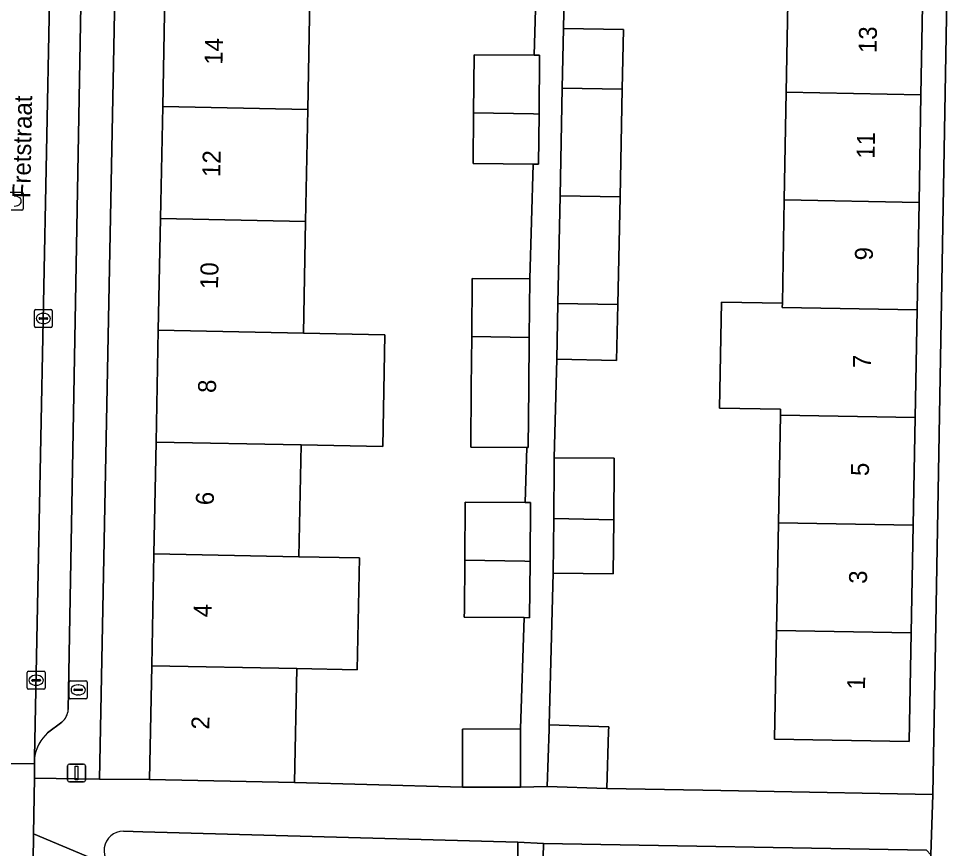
# Model space of a CAD drawing. Extents: x 160023 to 161302, y 384750 to 385707.
# Drawn here: x 160677 to 160728.6, y 385019.8 to 385066.1 of the extents above; entities that cross this region are included whole.
import ezdxf

# ---------------------------------------------------------------- set-up
doc = ezdxf.new("R2010")
doc.units = 0
for name, color, linetype in [('IMGEO_Brandkraan', 7, 'Continuous'), ('IMGEO_Erf', 7, 'Continuous'), ('IMGEO_Groenvoorziening', 7, 'Continuous'), ('IMGEO_Kolk', 7, 'Continuous'), ('IMGEO_Lichtmast', 7, 'Continuous'), ('IMGEO_Muur', 7, 'Continuous'), ('IMGEO_Openbare_ruimte_label', 7, 'Continuous'), ('IMGEO_Pand', 7, 'Continuous'), ('IMGEO_Pand_nummerreeks', 7, 'Continuous'), ('IMGEO_Parkeervlak_open', 7, 'Continuous'), ('IMGEO_Rijbaan_lokaal_gesloten', 7, 'Continuous'), ('IMGEO_Rijbaan_lokaal_open', 7, 'Continuous'), ('IMGEO_Rioolput', 7, 'Continuous'), ('IMGEO_Voetpad_open', 7, 'Continuous')]:
    doc.layers.add(name, color=color, linetype=linetype)

msp = doc.modelspace()

# ---------------------------------------------------------------- linework, layer by layer
at = {"layer": 'IMGEO_Brandkraan'}
for p, q in [((160679.828, 385028.254), (160679.828, 385029.106)), ((160679.903, 385029.18), (160680.755, 385029.18)), ((160680.829, 385029.106), (160680.829, 385028.254)), ((160680.087, 385028.674), (160680.087, 385028.686)), ((160680.525, 385028.637), (160680.127, 385028.637)), ((160680.13, 385028.723), (160680.528, 385028.723)), ((160680.316, 385028.96), (160680.341, 385028.96)), ((160680.571, 385028.686), (160680.571, 385028.674)), ((160680.755, 385028.18), (160679.903, 385028.18)), ((160680.339, 385028.4), (160680.314, 385028.4))]:
    msp.add_line(p, q, dxfattribs=at)
for points in [[(160679.828, 385028.254), (160679.828, 385029.106)], [(160679.903, 385029.18), (160680.755, 385029.18)], [(160680.829, 385029.106), (160680.829, 385028.254)], [(160680.755, 385028.18), (160679.903, 385028.18)]]:
    msp.add_lwpolyline(points, dxfattribs=at)
for centre, radius, start, end in [((160679.905, 385029.104), 0.0765, 91.552, 178.448), ((160679.905, 385029.104), 0.0765, 91.552, 178.448), ((160680.753, 385029.104), 0.0765, 1.552, 88.448), ((160680.753, 385029.104), 0.0765, 1.552, 88.448), ((160680.127, 385028.683), 0.0403, 85.8775, 175.7526), ((160680.124, 385028.673), 0.0366, 178.938, 274.7102), ((160680.528, 385028.68), 0.043, 264.8664, 352.4533), ((160680.532, 385028.685), 0.0386, 1.7309, 96.639), ((160679.905, 385028.256), 0.0765, 181.552, 268.448), ((160679.905, 385028.256), 0.0765, 181.552, 268.448), ((160680.753, 385028.256), 0.0765, 271.552, 358.448), ((160680.753, 385028.256), 0.0765, 271.552, 358.448)]:
    msp.add_arc(centre, radius, start, end, dxfattribs=at)
for centre, major_axis, ratio, start_param, end_param in [((160680.315, 385028.68), (-0.387, 0.002), 0.722429, 4.712389, 7.853982), ((160680.34, 385028.68), (-0.39, 0.002), 0.717154, 1.570796, 4.712389)]:
    msp.add_ellipse(centre, major_axis=major_axis, ratio=ratio, start_param=start_param, end_param=end_param, dxfattribs=at)
at = {"layer": 'IMGEO_Erf'}
msp.add_lwpolyline([(160682.973, 385098.744), (160681.51, 385023.71), (160684.298, 385023.676), (160684.423, 385030.023), (160684.546, 385036.256), (160684.67, 385042.49), (160684.793, 385048.724), (160684.916, 385054.958), (160685.039, 385061.192), (160685.162, 385067.425), (160685.285, 385073.659), (160685.408, 385079.893), (160685.531, 385086.127), (160685.655, 385092.36), (160685.78, 385098.711)], close=True, dxfattribs=at)
for points in [[(160707.438, 385068.318), (160707.381, 385065.557), (160710.722, 385065.487), (160710.652, 385062.16), (160710.527, 385056.16), (160710.402, 385050.161), (160710.337, 385047.05), (160706.998, 385047.12), (160706.865, 385041.619), (160710.209, 385041.591), (160710.206, 385041.222), (160710.18, 385038.163), (160710.154, 385035.153), (160706.81, 385035.182), (160706.581, 385026.724), (160709.897, 385026.616), (160709.889, 385026.38), (160709.785, 385023.182), (160715.135, 385023.083), (160718.134, 385023.028), (160727.96, 385022.845), (160729.292, 385097.92)], [(160693.246, 385067.266), (160693.122, 385061.033), (160692.999, 385054.799), (160692.876, 385048.565), (160697.421, 385048.476), (160697.298, 385042.242), (160692.753, 385042.331), (160692.63, 385036.097), (160695.998, 385036.031), (160695.876, 385029.798), (160692.506, 385029.864), (160692.381, 385023.516), (160696.42, 385023.404), (160701.751, 385023.256), (160701.743, 385026.495), (160704.972, 385026.502), (160705.184, 385032.705), (160701.849, 385032.734), (160701.852, 385033.081), (160701.877, 385035.915), (160701.904, 385039.149), (160705.248, 385039.121), (160705.341, 385042.19), (160702.208, 385042.217), (160702.238, 385045.548), (160702.262, 385048.38), (160702.291, 385051.616), (160705.494, 385051.589), (160705.688, 385057.988), (160702.344, 385058.017), (160702.369, 385060.851), (160702.396, 385064.085), (160705.74, 385064.057), (160705.935, 385070.455)], [(160727.413, 385067.857), (160727.304, 385061.858), (160727.195, 385055.858), (160727.086, 385049.859), (160726.978, 385043.86), (160726.869, 385037.861), (160726.76, 385031.862), (160726.65, 385025.798), (160719.138, 385025.934), (160719.248, 385031.998), (160719.357, 385037.997), (160719.466, 385043.996), (160719.472, 385044.323), (160716.076, 385044.384), (160716.182, 385050.299), (160719.578, 385050.238), (160719.683, 385055.994), (160719.792, 385061.994), (160719.901, 385067.993)]]:
    msp.add_lwpolyline(points, dxfattribs=at)
at = {"layer": 'IMGEO_Groenvoorziening'}
for points in [[(160683.921, 385020.768), (160682.843, 385020.799)], [(160704.782, 385014.119), (160704.836, 385020.196), (160683.921, 385020.768)]]:
    msp.add_lwpolyline(points, dxfattribs=at)
msp.add_lwpolyline([(160727.743, 385013.364), (160727.856, 385019.479), (160727.606, 385019.739), (160706.266, 385020.111), (160706.111, 385014.075)], close=True, dxfattribs=at)
msp.add_arc((160682.836, 385019.732), 1.067, 89.6283, 254.617, dxfattribs=at)
at = {"layer": 'IMGEO_Kolk'}
for p, q in [((160677.883, 385048.957), (160677.883, 385049.809)), ((160677.958, 385049.883), (160678.81, 385049.883)), ((160678.371, 385049.663), (160678.396, 385049.663)), ((160678.884, 385049.809), (160678.884, 385048.957)), ((160678.142, 385049.377), (160678.142, 385049.389)), ((160678.58, 385049.34), (160678.182, 385049.34)), ((160678.185, 385049.426), (160678.583, 385049.426)), ((160678.394, 385049.103), (160678.369, 385049.103)), ((160678.626, 385049.389), (160678.626, 385049.377)), ((160678.81, 385048.883), (160677.958, 385048.883)), ((160677.484, 385028.787), (160677.484, 385029.639)), ((160677.559, 385029.713), (160678.411, 385029.713)), ((160677.972, 385029.493), (160677.997, 385029.493)), ((160678.485, 385029.639), (160678.485, 385028.787)), ((160677.743, 385029.207), (160677.743, 385029.219)), ((160678.181, 385029.17), (160677.783, 385029.17)), ((160677.786, 385029.256), (160678.184, 385029.256)), ((160678.227, 385029.219), (160678.227, 385029.207)), ((160678.411, 385028.713), (160677.559, 385028.713)), ((160677.995, 385028.933), (160677.97, 385028.933))]:
    msp.add_line(p, q, dxfattribs=at)
for points in [[(160677.883, 385048.957), (160677.883, 385049.809)], [(160677.958, 385049.883), (160678.81, 385049.883)], [(160678.884, 385049.809), (160678.884, 385048.957)], [(160678.81, 385048.883), (160677.958, 385048.883)], [(160677.484, 385028.787), (160677.484, 385029.639)], [(160677.559, 385029.713), (160678.411, 385029.713)], [(160678.485, 385029.639), (160678.485, 385028.787)], [(160678.411, 385028.713), (160677.559, 385028.713)]]:
    msp.add_lwpolyline(points, dxfattribs=at)
for centre, radius, start, end in [((160677.96, 385049.807), 0.0765, 91.552, 178.448), ((160677.96, 385049.807), 0.0765, 91.552, 178.448), ((160678.808, 385049.807), 0.0765, 1.552, 88.448), ((160678.808, 385049.807), 0.0765, 1.552, 88.448), ((160678.182, 385049.386), 0.0403, 85.8775, 175.7526), ((160678.179, 385049.376), 0.0366, 178.938, 274.7102), ((160678.583, 385049.383), 0.043, 264.8664, 352.4533), ((160678.587, 385049.388), 0.0386, 1.7309, 96.639), ((160677.96, 385048.959), 0.0765, 181.552, 268.448), ((160677.96, 385048.959), 0.0765, 181.552, 268.448), ((160678.808, 385048.959), 0.0765, 271.552, 358.448), ((160678.808, 385048.959), 0.0765, 271.552, 358.448), ((160677.561, 385029.637), 0.0765, 91.552, 178.448), ((160677.561, 385029.637), 0.0765, 91.552, 178.448), ((160678.409, 385029.637), 0.0765, 1.552, 88.448), ((160678.409, 385029.637), 0.0765, 1.552, 88.448), ((160677.783, 385029.216), 0.0403, 85.8775, 175.7526), ((160677.78, 385029.206), 0.0366, 178.938, 274.7102), ((160678.184, 385029.213), 0.043, 264.8664, 352.4533), ((160678.188, 385029.218), 0.0386, 1.7309, 96.639), ((160677.561, 385028.789), 0.0765, 181.552, 268.448), ((160677.561, 385028.789), 0.0765, 181.552, 268.448), ((160678.409, 385028.789), 0.0765, 271.552, 358.448), ((160678.409, 385028.789), 0.0765, 271.552, 358.448)]:
    msp.add_arc(centre, radius, start, end, dxfattribs=at)
for centre, major_axis, ratio, start_param, end_param in [((160678.37, 385049.383), (-0.387, 0.002), 0.722429, 4.712389, 7.853982), ((160678.395, 385049.383), (-0.39, 0.002), 0.717154, 1.570796, 4.712389), ((160677.971, 385029.213), (-0.387, 0.002), 0.722429, 4.712389, 7.853982), ((160677.996, 385029.213), (-0.39, 0.002), 0.717154, 1.570796, 4.712389)]:
    msp.add_ellipse(centre, major_axis=major_axis, ratio=ratio, start_param=start_param, end_param=end_param, dxfattribs=at)
at = {"layer": 'IMGEO_Lichtmast'}
for p, q in [((160679.738, 385023.645), (160679.738, 385024.445)), ((160679.738, 385024.445), (160679.738, 385023.645)), ((160679.838, 385024.545), (160680.628, 385024.545)), ((160680.628, 385024.545), (160679.838, 385024.545)), ((160680.728, 385024.445), (160680.728, 385023.645)), ((160680.728, 385023.645), (160680.728, 385024.445)), ((160680.628, 385023.545), (160679.838, 385023.545)), ((160679.838, 385023.545), (160680.628, 385023.545))]:
    msp.add_line(p, q, dxfattribs=at)
msp.add_lwpolyline([(160680.158, 385024.42), (160680.308, 385024.42), (160680.308, 385023.67), (160680.158, 385023.67), (160680.158, 385024.42)], dxfattribs=at)
for centre, start, end in [((160679.838, 385024.445), 90, 180), ((160679.838, 385024.445), 90, 180), ((160680.628, 385024.445), 0, 90), ((160680.628, 385024.445), 360, 90), ((160679.838, 385023.645), 180, 270), ((160679.838, 385023.645), 180, 270), ((160680.628, 385023.645), 270, 0), ((160680.628, 385023.645), 270, 0)]:
    msp.add_arc(centre, 0.1, start, end, dxfattribs=at)
at = {"layer": 'IMGEO_Muur'}
for points in [[(160692.381, 385023.516), (160696.42, 385023.404)], [(160715.135, 385023.083), (160718.134, 385023.028)]]:
    msp.add_lwpolyline(points, dxfattribs=at)
at = {"layer": 'IMGEO_Pand'}
for points in [[(160727.304, 385061.858), (160727.413, 385067.857), (160719.901, 385067.993), (160719.792, 385061.994)], [(160685.162, 385067.425), (160685.039, 385061.192), (160693.122, 385061.033), (160693.246, 385067.266)], [(160707.381, 385065.557), (160707.312, 385062.22), (160710.652, 385062.16), (160710.722, 385065.487)], [(160705.74, 385064.057), (160702.396, 385064.085), (160702.369, 385060.851), (160705.712, 385060.785), (160706.016, 385060.779), (160706.043, 385064.054)], [(160710.652, 385062.16), (160707.312, 385062.22), (160707.187, 385056.22), (160710.527, 385056.16)], [(160719.792, 385061.994), (160719.683, 385055.994), (160727.195, 385055.858), (160727.304, 385061.858)], [(160685.039, 385061.192), (160684.916, 385054.958), (160692.999, 385054.799), (160693.122, 385061.033)], [(160706.016, 385060.779), (160705.712, 385060.785), (160702.369, 385060.851), (160702.344, 385058.017), (160705.688, 385057.988), (160705.992, 385057.985)], [(160710.527, 385056.16), (160707.187, 385056.22), (160707.063, 385050.222), (160710.402, 385050.161)], [(160727.195, 385055.858), (160719.683, 385055.994), (160719.578, 385050.238), (160719.574, 385049.995), (160727.086, 385049.859)], [(160684.916, 385054.958), (160684.793, 385048.724), (160692.876, 385048.565), (160692.999, 385054.799)], [(160705.494, 385051.589), (160702.291, 385051.616), (160702.262, 385048.38), (160705.466, 385048.317)], [(160710.402, 385050.161), (160707.063, 385050.222), (160706.998, 385047.12), (160710.337, 385047.05)], [(160727.086, 385049.859), (160719.574, 385049.995), (160719.578, 385050.238), (160716.182, 385050.299), (160716.076, 385044.384), (160719.472, 385044.323), (160719.466, 385043.996), (160726.978, 385043.86)], [(160697.421, 385048.476), (160692.876, 385048.565), (160684.793, 385048.724), (160684.67, 385042.49), (160692.753, 385042.331), (160697.298, 385042.242)], [(160705.442, 385045.52), (160705.466, 385048.317), (160702.262, 385048.38), (160702.238, 385045.548), (160702.208, 385042.217), (160705.341, 385042.19), (160705.413, 385042.189)], [(160726.869, 385037.861), (160726.978, 385043.86), (160719.466, 385043.996), (160719.357, 385037.997)], [(160684.67, 385042.49), (160684.546, 385036.256), (160692.63, 385036.097), (160692.753, 385042.331)], [(160710.206, 385041.222), (160710.209, 385041.591), (160706.865, 385041.619), (160706.862, 385041.251), (160706.836, 385038.224), (160710.18, 385038.163)], [(160705.248, 385039.121), (160701.904, 385039.149), (160701.877, 385035.915), (160705.22, 385035.849), (160705.513, 385035.843), (160705.541, 385039.119)], [(160706.81, 385035.182), (160710.154, 385035.153), (160710.18, 385038.163), (160706.836, 385038.224)], [(160726.76, 385031.862), (160726.869, 385037.861), (160719.357, 385037.997), (160719.248, 385031.998)], [(160695.998, 385036.031), (160692.63, 385036.097), (160684.546, 385036.256), (160684.423, 385030.023), (160692.506, 385029.864), (160695.876, 385029.798)], [(160705.513, 385035.843), (160705.22, 385035.849), (160701.877, 385035.915), (160701.852, 385033.081), (160701.849, 385032.734), (160705.184, 385032.705), (160705.486, 385032.702)], [(160719.248, 385031.998), (160719.138, 385025.934), (160726.65, 385025.798), (160726.76, 385031.862)], [(160692.381, 385023.516), (160692.506, 385029.864), (160684.423, 385030.023), (160684.298, 385023.676)], [(160704.98, 385023.264), (160704.972, 385026.502), (160701.743, 385026.495), (160701.751, 385023.256)], [(160709.889, 385026.38), (160709.897, 385026.616), (160706.581, 385026.724), (160706.573, 385026.487), (160706.469, 385023.289), (160709.785, 385023.182)]]:
    msp.add_lwpolyline(points, close=True, dxfattribs=at)
at = {"layer": 'IMGEO_Parkeervlak_open'}
for points in [[(160679.773, 385027.58), (160680.512, 385068.909), (160678.765, 385068.939), (160678.733, 385067.098), (160677.899, 385024.915)], [(160678.621, 385026.276), (160679.419, 385026.881)]]:
    msp.add_lwpolyline(points, dxfattribs=at)
for centre, radius, start, end in [((160678.704, 385027.682), 1.074, 311.7433, 354.538), ((160680.067, 385024.637), 2.186, 131.4192, 172.6896)]:
    msp.add_arc(centre, radius, start, end, dxfattribs=at)
at = {"layer": 'IMGEO_Rijbaan_lokaal_gesloten'}
msp.add_lwpolyline([(160677.84, 385020.653), (160677.883, 385023.76), (160677.894, 385024.55), (160674.398, 385024.598), (160674.322, 385022.108), (160674.225, 385018.942), (160672.047, 385019.862), (160667.501, 385021.654), (160665.07, 385015.82), (160679.636, 385009.86), (160682.074, 385015.664), (160681.717, 385015.811), (160677.797, 385017.49)], close=True, dxfattribs=at)
at = {"layer": 'IMGEO_Rijbaan_lokaal_open'}
msp.add_lwpolyline([(160677.894, 385024.55), (160677.899, 385024.915), (160678.733, 385067.098), (160678.765, 385068.939), (160675.267, 385069), (160675.231, 385066.698), (160674.883, 385049.401), (160674.474, 385029.308), (160674.41, 385024.986), (160674.398, 385024.598)], close=True, dxfattribs=at)
at = {"layer": 'IMGEO_Rioolput'}
for p, q in [((160676.328, 385056.427), (160677.18, 385056.427)), ((160677.254, 385056.353), (160677.254, 385055.501)), ((160677.18, 385055.427), (160676.328, 385055.427))]:
    msp.add_line(p, q, dxfattribs=at)
for points in [[(160676.328, 385056.427), (160677.18, 385056.427)], [(160677.254, 385056.353), (160677.254, 385055.501)], [(160677.18, 385055.427), (160676.328, 385055.427)]]:
    msp.add_lwpolyline(points, dxfattribs=at)
for centre, start, end in [((160677.178, 385056.351), 1.552, 88.448), ((160677.178, 385056.351), 1.552, 88.448), ((160677.178, 385055.503), 271.552, 358.448), ((160677.178, 385055.503), 271.552, 358.448)]:
    msp.add_arc(centre, 0.0765, start, end, dxfattribs=at)
msp.add_ellipse((160676.765, 385055.927), major_axis=(-0.39, 0.002), ratio=0.717154, start_param=1.570796, end_param=4.712389, dxfattribs=at)
at = {"layer": 'IMGEO_Voetpad_open'}
for points in [[(160681.548, 385127.317), (160681.162, 385104.326), (160682.202, 385104.305), (160682.085, 385098.627), (160681.044, 385098.648), (160680.562, 385071.689), (160680.512, 385068.909), (160679.773, 385027.58)], [(160729.89, 385127.033), (160729.433, 385103.068), (160718.095, 385103.244), (160714.896, 385103.294), (160709.624, 385103.376), (160706.463, 385103.423), (160706.382, 385098.342), (160707.892, 385098.297), (160711.275, 385098.232), (160720.446, 385098.051), (160727.958, 385097.915), (160729.292, 385097.92), (160727.96, 385022.845), (160727.856, 385019.479), (160727.743, 385013.364), (160727.588, 385004.93)], [(160677.899, 385024.915), (160677.894, 385024.55), (160677.883, 385023.76), (160681.51, 385023.71), (160682.973, 385098.744), (160685.78, 385098.711), (160693.864, 385098.551), (160703.174, 385098.369), (160706.382, 385098.342), (160706.463, 385103.423)], [(160705.935, 385070.455), (160705.74, 385064.057), (160706.043, 385064.054), (160706.016, 385060.779), (160705.992, 385057.985), (160705.688, 385057.988), (160705.494, 385051.589), (160705.466, 385048.317), (160705.442, 385045.52), (160705.413, 385042.189), (160705.341, 385042.19), (160705.248, 385039.121), (160705.541, 385039.119), (160705.513, 385035.843), (160705.486, 385032.702), (160705.184, 385032.705), (160704.972, 385026.502), (160704.98, 385023.264), (160706.469, 385023.289), (160706.573, 385026.487), (160706.581, 385026.724), (160706.81, 385035.182), (160706.836, 385038.224), (160706.862, 385041.251), (160706.865, 385041.619), (160706.998, 385047.12), (160707.063, 385050.222), (160707.187, 385056.22), (160707.312, 385062.22), (160707.381, 385065.557), (160707.438, 385068.318)], [(160679.419, 385026.881), (160678.621, 385026.276)], [(160727.96, 385022.845), (160718.134, 385023.028), (160715.135, 385023.083), (160709.785, 385023.182), (160706.469, 385023.289), (160704.98, 385023.264), (160701.751, 385023.256), (160696.42, 385023.404), (160692.381, 385023.516), (160684.298, 385023.676), (160681.51, 385023.71), (160677.883, 385023.76), (160677.84, 385020.653), (160682.396, 385018.74), (160682.553, 385018.703)], [(160682.843, 385020.799), (160683.921, 385020.768), (160704.836, 385020.196), (160706.266, 385020.111), (160727.606, 385019.739), (160727.856, 385019.479), (160727.96, 385022.845)]]:
    msp.add_lwpolyline(points, dxfattribs=at)
msp.add_lwpolyline([(160695.927, 385013.315), (160683.89, 385018.126), (160682.553, 385018.703), (160682.396, 385018.74), (160677.84, 385020.653), (160677.797, 385017.49), (160681.717, 385015.811), (160682.074, 385015.664), (160697.94, 385009.125), (160714.057, 385002.695), (160718.686, 385000.836), (160724.753, 384998.385), (160725.512, 384998.106), (160731.322, 384995.803), (160731.394, 384998.726), (160723.255, 385002.15), (160705.986, 385009.198), (160706.111, 385014.075), (160706.266, 385020.111), (160704.836, 385020.196), (160704.782, 385014.119), (160704.743, 385009.791)], close=True, dxfattribs=at)
for centre, radius, start, end in [((160678.704, 385027.682), 1.074, 311.7433, 354.538), ((160680.067, 385024.637), 2.186, 131.4192, 172.6896), ((160682.836, 385019.732), 1.067, 89.6283, 254.617)]:
    msp.add_arc(centre, radius, start, end, dxfattribs=at)

# ---------------------------------------------------------------- texts
at = {"layer": 'IMGEO_Openbare_ruimte_label'}
msp.add_text('Fretstraat', height=1, rotation=88.9115, dxfattribs=at).set_placement((160677.653, 385056.082))
at = {"layer": 'IMGEO_Pand_nummerreeks'}
for s, rotation, p in [('13', 88.9609, (160724.825, 385064.172)), ('14', 88.8685, (160688.366, 385063.52)), ('11', 88.9609, (160724.718, 385058.276)), ('12', 88.8685, (160688.243, 385057.264)), ('9', 88.9632, (160724.616, 385052.612)), ('10', 88.8685, (160688.119, 385051.017)), ('7', 88.9632, (160724.507, 385046.603)), ('8', 88.8658, (160688.004, 385045.225)), ('5', 88.9609, (160724.398, 385040.593)), ('6', 88.8685, (160687.881, 385038.968)), ('3', 88.9609, (160724.289, 385034.583)), ('4', 88.8658, (160687.757, 385032.715)), ('1', 88.9609, (160724.182, 385028.687)), ('2', 88.8685, (160687.634, 385026.46))]:
    msp.add_text(s, height=1, rotation=rotation, dxfattribs=at).set_placement(p)

doc.saveas('drawing.dxf')
